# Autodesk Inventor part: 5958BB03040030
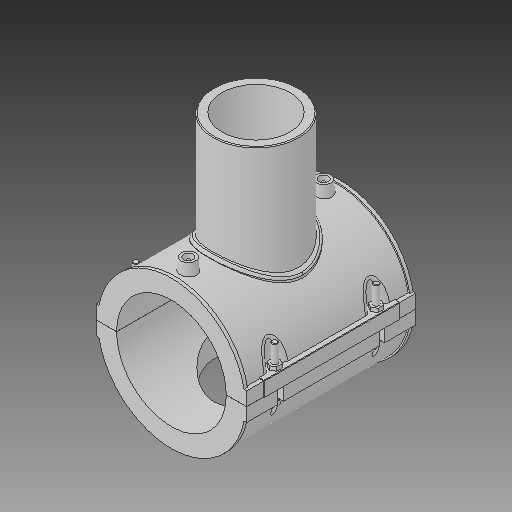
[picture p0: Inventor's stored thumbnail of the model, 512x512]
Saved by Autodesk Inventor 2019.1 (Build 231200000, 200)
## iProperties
Created: 2017-07
Part Number: 5958BB03040030
Material: Generic
Description: PLASSON BRANCH SADDLE 4'' x 3''
Document SubType Name: Modeling
Designer: KIM
Mass: 764.267 g
Surface Area: 1930.38 cm^2
Volume: 764.267 cm^3
Density: 1 g/cm^3
Appearance: Default
Author: KIM
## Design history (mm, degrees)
derived "5958B.ipt"
feature "Solid1::5958B.ipt"
feature "Solid2::5958B.ipt"
feature "Solid3::5958B.ipt"
tag "TaggingFeature1"
body "Solid1"
body "Solid2"
body "Solid3"
other parameters: "d_" = 114.1, "B_" = 156.464, "H_" = 106.934, "L_" = 176.022, "d_t" = 6, "d_1" = 88.7, "H_1" = 88.646, "d1" = 150.676, "d148" = 2.8525, "d160" = 2.8525, "d0" = 114.1, "d2" = 156.464, "d3" = 28.525, "d4" = 176.022, "d5" = 0, "d6" = 0.1, "d8" = 0, "d19" = 6, "d20" = 6, "d21" = 105.6132, "d23" = 0, "d24" = 52.8066, "d26" = 0, "d27" = 3, "d28" = 3, "d29" = 3, "d30" = 38.03333, "d31" = 6, "d32" = 0, "d33" = 0, "d34" = 0.6, "d40" = 78.35152, "d41" = 97.57, "d43" = 0, "d45" = 0, "d47" = 182.272, "d48" = 88.7, "d50" = 0, "d70" = 15, "d72" = 0, "d73" = 6, "d75" = 5, "d76" = 0, "d77" = 5.705, "d78" = 87.05, "d79" = 15, "d80" = 70.4088, "d82" = 5 deg, "d84" = 4, "d85" = 14, "d86" = 0, "d87" = 3, "d88" = 0, "d89" = 1, "d90" = 1, "d91" = 140.8176, "d92" = 0, "d93" = 0.5, "d94" = 60.05263, "d96" = 153.68952, "d97" = 3.52044, "d98" = 0, "d102" = 2.661, "d103" = 70.96, "d105" = 0, "d109" = -35.64467, "d117" = 0.887, "d120" = 140 deg, "d121" = 24.228, "d122" = 20 deg, "d123" = 301.352, "d124" = 90.4056, "d126" = 0, "d143" = 119.805, "d150" = 20.538, "d159" = 7.3152, "d161" = 2.8525, "d162" = 105.6132, "d163" = 0, "d167" = 22.82, "d168" = 68.48909, "d173" = 1, "d175" = 57.05, "d176" = 20 deg, "d177" = 7.987, "d178" = 36.576, "d180" = 0, "d185" = 57.20715, "d186" = 57.20715, "d187" = 75.338, "d188" = 10.9728, "d189" = 7.987, "d190" = 0, "d191" = 113.007, "d200" = 18.288, "d202" = 0, "d216" = 158.4198, "d217" = 0, "d221" = 65.12814, "d222" = 7.987, "d223" = 4.7922, "d224" = 57.05, "d225" = 4.7922, "d227" = 16.4304, "d230" = 70.742, "d236" = 11.5 deg, "d238" = 20 deg, "d239" = 7.987, "d240" = 0, "d241" = 0, "d242" = 6.2484
